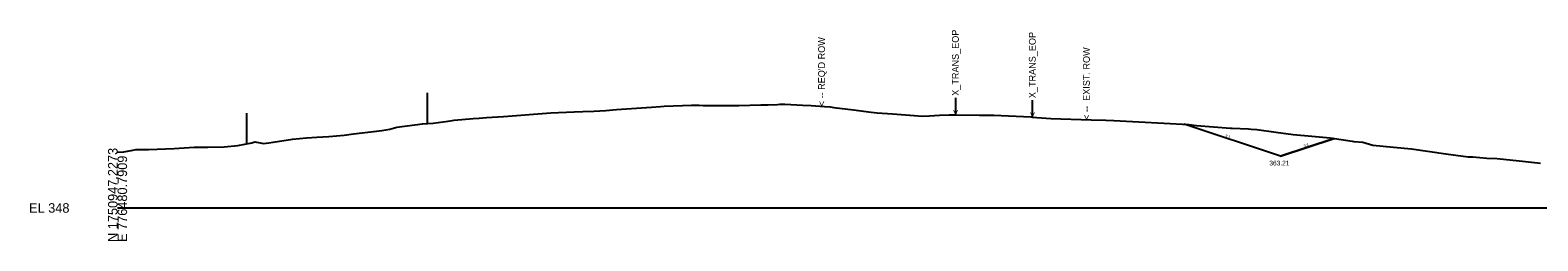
# Model space of a CAD drawing. Extents: x 776426 to 854588, y 1736205 to 1756790.
# Drawn here: x 804645.1 to 805088.3, y 1756205.1 to 1756267.1 of the extents above; entities that cross this region are included whole.
import ezdxf

# ---------------------------------------------------------------- set-up
doc = ezdxf.new("R2010")
doc.units = 0
for name, color, linetype in [('DTM CONTOURS_MAJOR_TX', 7, 'Continuous'), ('DTM_X_FLOW_ARROWS', 7, 'Continuous'), ('TRANS_UNPAVED_SHOULDERS', 7, 'Continuous'), ('X_TRANS_EOP', 7, 'Continuous'), ('XS_M_SHAPES_EARTHWORK', 7, 'Continuous'), ('XS_P_FINISHED_GRADE', 7, 'Continuous'), ('XS_P_ROW', 7, 'Continuous'), ('XS_P_TX_DCH', 7, 'Continuous'), ('XS_P_TX_FS_BS', 7, 'Continuous'), ('XS_X_PAVEMENT', 7, 'Continuous'), ('XS_X_ROW', 7, 'Continuous')]:
    doc.layers.add(name, color=color, linetype=linetype)

msp = doc.modelspace()

# ---------------------------------------------------------------- linework, layer by layer
at = {"layer": 'DTM CONTOURS_MAJOR_TX'}
msp.add_line((804670.79, 1756214.76), (805170.79, 1756214.76), dxfattribs=at)
at = {"layer": 'DTM_X_FLOW_ARROWS'}
msp.add_lwpolyline([(804670.79, 1756231.17), (804672.68, 1756231.28), (804675.31, 1756231.8), (804676.19, 1756231.92), (804678.03, 1756231.98), (804678.72, 1756231.97), (804679.91, 1756231.92), (804687.44, 1756232.3), (804693.27, 1756232.61), (804694.36, 1756232.65), (804697.32, 1756232.67), (804702.14, 1756232.77), (804706.19, 1756233.11), (804710.22, 1756233.98), (804711.13, 1756234.18), (804712.71, 1756233.91), (804713.73, 1756233.7), (804715.25, 1756233.91), (804716.55, 1756234.14), (804722.21, 1756235.03), (804726.35, 1756235.39), (804729.41, 1756235.58), (804732.91, 1756235.81), (804737.4, 1756236.2), (804740.17, 1756236.54), (804746.9, 1756237.35), (804748.49, 1756237.54), (804750.86, 1756237.94), (804752.89, 1756238.53), (804760.42, 1756239.54), (804763.57, 1756239.7), (804767.96, 1756240.34), (804769.73, 1756240.58), (804775.32, 1756241.08), (804777.05, 1756241.22), (804779.24, 1756241.34), (804780.89, 1756241.48), (804784.24, 1756241.73), (804798.17, 1756242.76), (804805.06, 1756243.04), (804807.6, 1756243.13), (804810.8, 1756243.29), (804814.28, 1756243.45), (804817.45, 1756243.77), (804827.77, 1756244.47), (804830.39, 1756244.66), (804831.51, 1756244.71), (804839.55, 1756245), (804841.74, 1756244.98), (804842.98, 1756244.9), (804843.68, 1756244.89), (804844.43, 1756244.88), (804844.97, 1756244.88), (804845.41, 1756244.88), (804846.32, 1756244.9), (804852.16, 1756244.91), (804853.47, 1756244.93), (804859.88, 1756245.11), (804862.07, 1756245.16), (804864.81, 1756245.24), (804865.46, 1756245.27), (804866.91, 1756245.32), (804870.5, 1756245.15), (804872.09, 1756245.06), (804874.65, 1756244.89), (804878.58, 1756244.64), (804880.25, 1756244.5), (804881.34, 1756244.35), (804887.15, 1756243.61), (804892.35, 1756242.92), (804894.07, 1756242.75), (804898.58, 1756242.43), (804905, 1756241.95), (804907.33, 1756241.74), (804909.46, 1756241.86), (804912.45, 1756242.06), (804915.24, 1756242.18), (804917.09, 1756242.21), (804924.15, 1756242.1), (804928.41, 1756242.12), (804939.23, 1756241.55), (804939.69, 1756241.52), (804945.12, 1756241.08), (804957.02, 1756240.67), (804961.34, 1756240.57), (804963.67, 1756240.47), (804985.67, 1756239.32), (804987.92, 1756239.02), (804997.93, 1756238.23), (804998.43, 1756238.21), (805003.21, 1756238.04), (805004.05, 1756237.96), (805005.72, 1756237.87), (805011.28, 1756237.08), (805016.42, 1756236.41), (805021.88, 1756235.91), (805027.26, 1756235.44), (805033.69, 1756234.42), (805034.2, 1756234.35), (805036.82, 1756234.09), (805039.82, 1756233.24), (805045.91, 1756232.66), (805051.13, 1756232.13), (805061.23, 1756230.74), (805067.84, 1756229.84), (805069.2, 1756229.79), (805073.33, 1756229.44), (805076.34, 1756229.29), (805084.65, 1756228.47), (805089.11, 1756227.98)], dxfattribs=at)
at = {"layer": 'TRANS_UNPAVED_SHOULDERS'}
for p, q in [((804761.79, 1756248.61), (804761.79, 1756239.61)), ((804761.79, 1756248.61), (804761.79, 1756239.61)), ((804708.72, 1756242.65), (804708.72, 1756233.65)), ((804708.72, 1756242.65), (804708.72, 1756233.65))]:
    msp.add_line(p, q, dxfattribs=at)
at = {"layer": 'X_TRANS_EOP'}
for p, q in [((804917.09, 1756247.21), (804917.09, 1756242.21)), ((804917.09, 1756247.21), (804917.09, 1756242.21)), ((804939.69, 1756246.52), (804939.69, 1756241.52)), ((804939.69, 1756246.52), (804939.69, 1756241.52))]:
    msp.add_line(p, q, dxfattribs=at)
at = {"layer": 'XS_M_SHAPES_EARTHWORK'}
msp.add_lwpolyline([(805021.88, 1756235.91), (805027.26, 1756235.44), (805028.46, 1756235.25), (805012.62, 1756229.97), (804984.38, 1756239.39), (804985.67, 1756239.32), (804987.92, 1756239.02), (804997.93, 1756238.23), (804998.43, 1756238.21), (805003.21, 1756238.04), (805004.05, 1756237.96), (805005.72, 1756237.87), (805011.28, 1756237.08), (805016.42, 1756236.41)], close=True, dxfattribs=at)
at = {"layer": 'XS_P_FINISHED_GRADE'}
for q in [(804984.38, 1756239.39), (805028.46, 1756235.25)]:
    msp.add_line((805012.62, 1756229.97), q, dxfattribs=at)

# ---------------------------------------------------------------- texts
at = {"layer": 'DTM CONTOURS_MAJOR_TX'}
for s, p in [('N 1750947.2273', (804670.79, 1756204.76)), ('E 776480.7909', (804673.59, 1756204.76))]:
    msp.add_text(s, height=2.8, rotation=90, dxfattribs=at).set_placement(p)
msp.add_text('EL 348', height=2.8, dxfattribs=at).set_placement((804644.79, 1756213.36))
at = {"layer": 'XS_P_ROW'}
msp.add_text("< -- REQ'D ROW", height=2, rotation=90, dxfattribs=at).set_placement((804878.74, 1756244.69))
at = {"layer": 'XS_P_TX_DCH'}
msp.add_text('363.21', height=1.4, dxfattribs=at).set_placement((805009.38, 1756227.27))
at = {"layer": 'XS_P_TX_FS_BS'}
for rotation, p in [(341.5651, (804996.29, 1756235.68)), (18.4349, (805019.6, 1756232.61))]:
    msp.add_text('3:1', height=0.8, rotation=rotation, dxfattribs=at).set_placement(p)
at = {"layer": 'XS_X_PAVEMENT'}
for p in [(804918.09, 1756242.21), (804940.69, 1756241.52)]:
    msp.add_text('< --  X_TRANS_EOP', height=2, rotation=90, dxfattribs=at).set_placement(p)
at = {"layer": 'XS_X_ROW'}
msp.add_text('< --  EXIST. ROW', height=2, rotation=90, dxfattribs=at).set_placement((804956.6, 1756240.72))

doc.saveas('drawing.dxf')
